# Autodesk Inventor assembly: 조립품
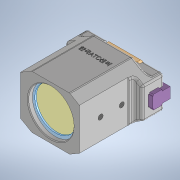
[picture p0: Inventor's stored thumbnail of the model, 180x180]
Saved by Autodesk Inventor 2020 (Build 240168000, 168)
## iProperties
Created: 2023-05
Part Number: 조립품
Document SubType Name: Assembly
Designer: oem
Author: oem
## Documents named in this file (12)
- C:\Users\oem\Desktop\730506V1008\조립품.iam
- C:\Users\oem\Desktop\730506V1008\본체.ipt
- C:\Users\oem\Desktop\730506V1008\C형 구멍용 멈춤링 60x2.ipt
- C:\Users\oem\Desktop\730506V1008\O링 P16.ipt
- C:\Users\oem\Desktop\730506V1008\O링 P44.ipt
- C:\Users\oem\Desktop\730506V1008\볼트 M3 x 6.ipt
- C:\Users\oem\Desktop\730506V1008\볼트 M6 x 12.ipt
- C:\Users\oem\Desktop\730506V1008\앤드캡.ipt
- C:\Users\oem\Desktop\730506V1008\척.ipt
- C:\Users\oem\Desktop\730506V1008\커버.ipt
- C:\Users\oem\Desktop\730506V1008\피스톤 로드.ipt
- C:\Users\oem\Desktop\730506V1008\피스톤.ipt
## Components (5 placed, 5 different names)
1. C형 구멍용 멈춤링 60x2:1
2. O링 P16:1
3. O링 P44:1
4. 피스톤 로드:1
5. 피스톤:1
